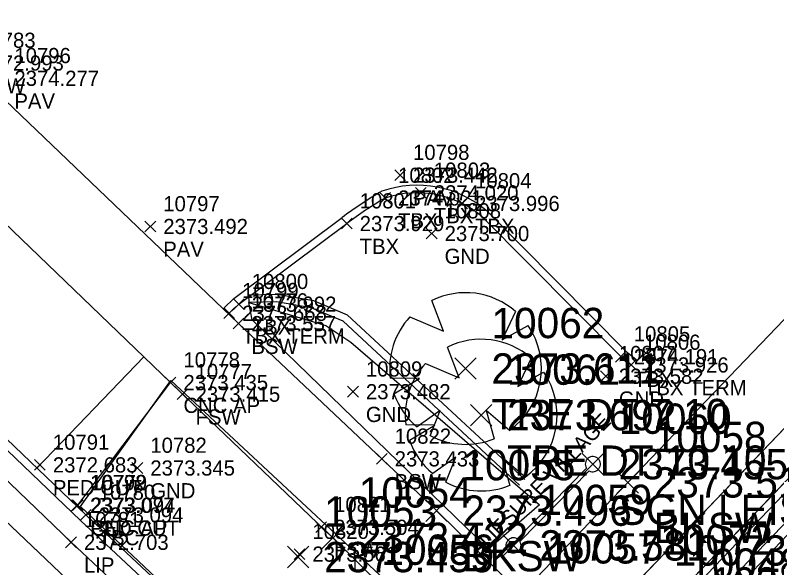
# Model space of a CAD drawing. Extents: x 2377639 to 2379738, y 729875 to 732734.
# Drawn here: x 2378105.9 to 2378156.1, y 730392.7 to 730429.2 of the extents above; entities that cross this region are included whole.
import ezdxf

# ---------------------------------------------------------------- set-up
doc = ezdxf.new("R2010")
doc.units = 0
for name, color, linetype in [('Default', 7, 'Continuous'), ('TOPO_CURBGTR_Back-of-Curb', 7, 'Continuous'), ('TOPO_CURBGTR_Face-of-Curb', 7, 'Continuous'), ('TOPO_CURBGTR_Lip-of-Gutter', 7, 'Continuous'), ('TOPO_DATA_Elevations', 7, 'Continuous'), ('TOPO_DATA_Notes', 7, 'Continuous'), ('TOPO_LNDSCP_Bush-Boundary', 7, 'Continuous'), ('TOPO_LNDSCP_Misc', 7, 'Continuous'), ('TOPO_LNDSCP_Tree', 7, 'Continuous'), ('TOPO_MISC_Flat-Asphalt', 7, 'Continuous'), ('TOPO_SIGNS_Post-Single', 7, 'Continuous'), ('TOPO_SW_Back', 7, 'Continuous'), ('TOPO_WTRUTIL_Fire-Hydrant', 7, 'Continuous'), ('TOPO_WTRUTIL_Line', 7, 'Continuous')]:
    doc.layers.add(name, color=color, linetype=linetype)

# ---------------------------------------------------------------- blocks, each defined once
blk = doc.blocks.new('DT_1')
at = {"layer": 'Default'}
for p, q in [((-0.037, 0.0625), (-0.0565, 0.1137)), ((0.0838, 0.0954), (0.0615, 0.0479)), ((-0.093, 0.0865), (-0.037, 0.0625)), ((0.0615, 0.0479), (0.1046, 0.072)), ((-0.0773, -0.017), (-0.1259, -0.0164)), ((-0.1198, -0.0422), (-0.0773, -0.017)), ((-0.0426, -0.0702), (-0.0811, -0.0977)), ((-0.059, -0.1125), (-0.0426, -0.0702)), ((0.0734, -0.1037), (0.0346, -0.0702)), ((0.0346, -0.0702), (0.048, -0.1176))]:
    blk.add_line(p, q, dxfattribs=at)
for start, end in [(48.7013, 116.3979), (137.0682, 187.4038), (305.2865, 34.5379), (199.3985, 230.3084), (242.3287, 292.2114)]:
    blk.add_arc((0, 0), 0.127, start, end, dxfattribs=at)

msp = doc.modelspace()

# ---------------------------------------------------------------- linework, layer by layer
at = {"layer": 'TOPO_CURBGTR_Back-of-Curb'}
for points in [[(2378139.753, 730380.865), (2378148.64, 730389.997), (2378225.837, 730470.65), (2378251.518, 730497.426), (2378309.295, 730557.655), (2378317.456, 730566.28)], [(2378136.696, 730415.869), (2378145.842, 730406.642), (2378146.514, 730406.094)], [(2378119.279, 730388.079), (2378110.587, 730396.202), (2378090.198, 730415.739)], [(2378120.038, 730409.502), (2378120.67, 730410.101), (2378127.78, 730415.416)], [(2378121.318, 730410.715), (2378123.198, 730410.754), (2378125.58, 730410.338), (2378127.817, 730409.406), (2378139.51, 730398.53)]]:
    msp.add_lwpolyline(points, dxfattribs=at)
for centre, radius, start, end in [((2378132.413, 730410.83), 6.613, 49.635, 108.5304), ((2378144.472, 730393.087), 27.879, 120.5274, 126.7795)]:
    msp.add_arc(centre, radius, start, end, dxfattribs=at)
at = {"layer": 'TOPO_CURBGTR_Face-of-Curb'}
msp.add_line((2378121.318, 730410.715), (2378121.328, 730410.215), dxfattribs=at)
for points in [[(2378140.262, 730380.667), (2378149, 730389.65), (2378226.198, 730470.304), (2378251.879, 730497.08), (2378309.657, 730557.31), (2378317.819, 730565.936)], [(2378119.694, 730409.865), (2378120.347, 730410.484), (2378127.481, 730415.816)], [(2378137.036, 730416.236), (2378146.178, 730407.013), (2378146.83, 730406.481)], [(2378118.938, 730387.713), (2378110.243, 730395.839), (2378089.852, 730415.378)], [(2378139.169, 730398.164), (2378127.542, 730408.979), (2378125.439, 730409.855), (2378123.16, 730410.254), (2378121.328, 730410.215)]]:
    msp.add_lwpolyline(points, dxfattribs=at)
for centre, radius, start, end in [((2378132.413, 730410.83), 7.113, 49.4599, 108.9593), ((2378144.472, 730393.087), 28.379, 120.4228, 126.7795)]:
    msp.add_arc(centre, radius, start, end, dxfattribs=at)
at = {"layer": 'TOPO_CURBGTR_Lip-of-Gutter'}
for points in [[(2378319.904, 730566.205), (2378310.745, 730556.446), (2378281.259, 730525.513), (2378150.03, 730388.754), (2378141.734, 730380.114)], [(2378088.895, 730414.34), (2378109.615, 730394.398), (2378117.945, 730386.574)]]:
    msp.add_lwpolyline(points, dxfattribs=at)
at = {"layer": 'TOPO_DATA_Elevations'}
for p, q in [((2378130.941, 730418.258), (2378131.649, 730418.966)), ((2378130.941, 730418.966), (2378131.649, 730418.258)), ((2378130.941, 730418.258), (2378131.649, 730418.966)), ((2378130.941, 730418.966), (2378131.649, 730418.258)), ((2378129.957, 730416.747), (2378130.665, 730417.455)), ((2378129.957, 730417.455), (2378130.665, 730416.747)), ((2378129.957, 730416.747), (2378130.665, 730417.455)), ((2378129.957, 730417.455), (2378130.665, 730416.747)), ((2378132.311, 730417.085), (2378133.019, 730417.793)), ((2378132.311, 730417.793), (2378133.019, 730417.085)), ((2378132.311, 730417.085), (2378133.019, 730417.793)), ((2378132.311, 730417.793), (2378133.019, 730417.085)), ((2378135.029, 730416.387), (2378135.737, 730417.095)), ((2378135.029, 730417.095), (2378135.737, 730416.387)), ((2378135.029, 730416.387), (2378135.737, 730417.095)), ((2378135.029, 730417.095), (2378135.737, 730416.387)), ((2378114.484, 730414.872), (2378115.192, 730415.58)), ((2378114.484, 730415.58), (2378115.192, 730414.872)), ((2378114.484, 730414.872), (2378115.192, 730415.58)), ((2378114.484, 730415.58), (2378115.192, 730414.872)), ((2378127.426, 730415.062), (2378128.134, 730415.77)), ((2378127.426, 730415.77), (2378128.134, 730415.062)), ((2378127.426, 730415.062), (2378128.134, 730415.77)), ((2378127.426, 730415.77), (2378128.134, 730415.062)), ((2378133.022, 730414.404), (2378133.73, 730415.112)), ((2378133.022, 730415.112), (2378133.73, 730414.404)), ((2378133.022, 730414.404), (2378133.73, 730415.112)), ((2378133.022, 730415.112), (2378133.73, 730414.404)), ((2378120.316, 730409.747), (2378121.024, 730410.455)), ((2378120.316, 730410.455), (2378121.024, 730409.747)), ((2378120.316, 730409.747), (2378121.024, 730410.455)), ((2378120.316, 730410.455), (2378121.024, 730409.747)), ((2378119.684, 730409.148), (2378120.392, 730409.856)), ((2378119.684, 730409.856), (2378120.392, 730409.148)), ((2378119.684, 730409.148), (2378120.392, 730409.856)), ((2378119.684, 730409.856), (2378120.392, 730409.148)), ((2378120.293, 730408.465), (2378121.001, 730409.173)), ((2378120.293, 730409.173), (2378121.001, 730408.465)), ((2378120.293, 730408.465), (2378121.001, 730409.173)), ((2378120.293, 730409.173), (2378121.001, 730408.465)), ((2378145.488, 730406.288), (2378146.196, 730406.996)), ((2378145.488, 730406.996), (2378146.196, 730406.288)), ((2378145.488, 730406.288), (2378146.196, 730406.996)), ((2378145.488, 730406.996), (2378146.196, 730406.288)), ((2378134.902, 730405.152), (2378136.316, 730406.566)), ((2378134.902, 730406.566), (2378136.316, 730405.152)), ((2378146.16, 730405.74), (2378146.868, 730406.448)), ((2378146.16, 730406.448), (2378146.868, 730405.74)), ((2378146.16, 730405.74), (2378146.868, 730406.448)), ((2378146.16, 730406.448), (2378146.868, 730405.74)), ((2378115.814, 730404.577), (2378116.522, 730405.285)), ((2378115.814, 730405.285), (2378116.522, 730404.577)), ((2378115.814, 730404.577), (2378116.522, 730405.285)), ((2378115.814, 730405.285), (2378116.522, 730404.577)), ((2378144.504, 730404.995), (2378145.212, 730405.703)), ((2378144.504, 730405.703), (2378145.212, 730404.995)), ((2378144.504, 730404.995), (2378145.212, 730405.703)), ((2378144.504, 730405.703), (2378145.212, 730404.995)), ((2378116.612, 730403.812), (2378117.32, 730404.52)), ((2378116.612, 730404.52), (2378117.32, 730403.812)), ((2378116.612, 730403.812), (2378117.32, 730404.52)), ((2378116.612, 730404.52), (2378117.32, 730403.812)), ((2378127.837, 730403.976), (2378128.545, 730404.684)), ((2378127.837, 730404.684), (2378128.545, 730403.976)), ((2378127.837, 730403.976), (2378128.545, 730404.684)), ((2378127.837, 730404.684), (2378128.545, 730403.976)), ((2378135.931, 730402.078), (2378137.345, 730403.492)), ((2378135.931, 730403.492), (2378137.345, 730402.078)), ((2378143.289, 730398.844), (2378144.703, 730400.258)), ((2378143.289, 730400.258), (2378144.703, 730398.844)), ((2378107.209, 730399.149), (2378107.917, 730399.857)), ((2378107.209, 730399.857), (2378107.917, 730399.149)), ((2378107.209, 730399.149), (2378107.917, 730399.857)), ((2378107.209, 730399.857), (2378107.917, 730399.149)), ((2378129.732, 730399.546), (2378130.439, 730400.254)), ((2378129.732, 730400.254), (2378130.439, 730399.546)), ((2378129.732, 730399.546), (2378130.439, 730400.254)), ((2378129.732, 730400.254), (2378130.439, 730399.546)), ((2378113.631, 730398.945), (2378114.339, 730399.653)), ((2378113.631, 730399.653), (2378114.339, 730398.945)), ((2378113.631, 730398.945), (2378114.339, 730399.653)), ((2378113.631, 730399.653), (2378114.339, 730398.945)), ((2378145.593, 730397.642), (2378147.007, 730399.056)), ((2378145.593, 730399.056), (2378147.007, 730397.642)), ((2378109.655, 730396.482), (2378110.363, 730397.19)), ((2378109.655, 730397.19), (2378110.363, 730396.482)), ((2378109.655, 730396.482), (2378110.363, 730397.19)), ((2378109.655, 730397.19), (2378110.363, 730396.482)), ((2378109.703, 730396.492), (2378110.411, 730397.2)), ((2378109.703, 730397.2), (2378110.411, 730396.492)), ((2378109.703, 730396.492), (2378110.411, 730397.2)), ((2378109.703, 730397.2), (2378110.411, 730396.492)), ((2378132.991, 730395.779), (2378134.405, 730397.193)), ((2378132.991, 730397.193), (2378134.405, 730395.779)), ((2378110.233, 730395.848), (2378110.941, 730396.556)), ((2378110.233, 730396.556), (2378110.941, 730395.848)), ((2378110.233, 730395.848), (2378110.941, 730396.556)), ((2378110.233, 730396.556), (2378110.941, 730395.848)), ((2378125.739, 730395.035), (2378126.447, 730395.743)), ((2378125.739, 730395.743), (2378126.447, 730395.035)), ((2378125.739, 730395.035), (2378126.447, 730395.743)), ((2378125.739, 730395.743), (2378126.447, 730395.035)), ((2378126.165, 730393.982), (2378127.579, 730395.396)), ((2378126.165, 730395.396), (2378127.579, 730393.982)), ((2378109.261, 730394.044), (2378109.969, 730394.752)), ((2378109.261, 730394.752), (2378109.969, 730394.044)), ((2378109.261, 730394.044), (2378109.969, 730394.752)), ((2378109.261, 730394.752), (2378109.969, 730394.044)), ((2378138.061, 730393.488), (2378139.475, 730394.902)), ((2378138.061, 730394.902), (2378139.475, 730393.488)), ((2378123.878, 730392.72), (2378125.292, 730394.134)), ((2378123.878, 730394.134), (2378125.292, 730392.72)), ((2378124.31, 730393.268), (2378125.018, 730393.976)), ((2378124.31, 730393.976), (2378125.018, 730393.268)), ((2378124.31, 730393.268), (2378125.018, 730393.976)), ((2378124.31, 730393.976), (2378125.018, 730393.268))]:
    msp.add_line(p, q, dxfattribs=at)
at = {"layer": 'TOPO_LNDSCP_Bush-Boundary'}
msp.add_lwpolyline([(2378140.474, 730396.86), (2378137.112, 730393.94), (2378121.559, 730409.079), (2378121.328, 730410.215), (2378126.403, 730408.704), (2378128.056, 730407.592)], close=True, dxfattribs=at)
at = {"layer": 'TOPO_LNDSCP_Misc'}
for points in [[(2378110.246, 730396.771), (2378116.19, 730405.07), (2378135.663, 730386.918)], [(2378135.663, 730386.918), (2378128.606, 730379.436), (2378110.246, 730396.771)]]:
    msp.add_lwpolyline(points, dxfattribs=at)
at = {"layer": 'TOPO_MISC_Flat-Asphalt'}
msp.add_lwpolyline([(2378142.932, 730387.645), (2378190.637, 730437.477), (2378192.437, 730435.754), (2378144.732, 730385.922)], close=True, dxfattribs=at)
at = {"layer": 'TOPO_SIGNS_Post-Single'}
for p, q in [((2378143.568, 730399.292), (2378139.017, 730394.629)), ((2378139.196, 730394.454), (2378143.747, 730399.117))]:
    msp.add_line(p, q, dxfattribs=at)
for centre, start, end in [((2378143.996, 730399.551), 240.1704, 211.2154), ((2378138.768, 730394.195), 60.1704, 31.2154)]:
    msp.add_arc(centre, 0.5, start, end, dxfattribs=at)
at = {"layer": 'TOPO_SW_Back'}
for p, q in [((2378107.361, 730399.293), (2378114.412, 730406.621)), ((2378109.997, 730396.767), (2378116.168, 730404.931))]:
    msp.add_line(p, q, dxfattribs=at)
for points in [[(2378133.698, 730396.486), (2378139.263, 730391), (2378146.3, 730398.349), (2378224.625, 730480.085)], [(2378224.032, 730472.38), (2378146.723, 730391.578), (2378142.932, 730387.645), (2378144.689, 730385.936)], [(2378102.707, 730426.003), (2378120.647, 730408.819), (2378133.698, 730396.486)], [(2378126.872, 730394.689), (2378116.168, 730404.931), (2378097.08, 730423.299)], [(2378126.872, 730394.689), (2378135.063, 730386.614), (2378128.358, 730379.611)]]:
    msp.add_lwpolyline(points, dxfattribs=at)
at = {"layer": 'TOPO_WTRUTIL_Fire-Hydrant'}
msp.add_line((2378128.332, 730392.495), (2378128.309, 730394.078), dxfattribs=at)
at = {"layer": 'TOPO_WTRUTIL_Line'}
for p, q in [((2378133.356, 730370.41), (2378391.806, 730640.09)), ((2377982.698, 730512.231), (2378121.502, 730380.425))]:
    msp.add_line(p, q, dxfattribs=at)

# ---------------------------------------------------------------- block references
at = {"layer": 'TOPO_LNDSCP_Tree', "xscale": 39.370000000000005, "yscale": 39.370000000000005}
for p in [(2378135.609, 730405.859), (2378136.638, 730402.785)]:
    msp.add_blockref('DT_1', p, dxfattribs=at)

# ---------------------------------------------------------------- texts
at = {"layer": 'TOPO_DATA_Elevations'}
for s, height, p in [('10783', 1, (2378103.561, 730427.003)), ('10783', 1, (2378103.561, 730427.003)), ('10796', 1, (2378105.884, 730425.996)), ('10796', 1, (2378105.884, 730425.996)), ('2372.993', 1, (2378103.561, 730425.503)), ('2372.993', 1, (2378103.561, 730425.503)), ('2374.277', 1, (2378105.884, 730424.496)), ('2374.277', 1, (2378105.884, 730424.496)), ('BSW', 1, (2378103.561, 730424.003)), ('BSW', 1, (2378103.561, 730424.003)), ('PAV', 1, (2378105.884, 730422.996)), ('PAV', 1, (2378105.884, 730422.996)), ('10798', 1, (2378132.149, 730419.612)), ('10798', 1, (2378132.149, 730419.612)), ('10803', 1, (2378133.519, 730418.439)), ('10803', 1, (2378133.519, 730418.439)), ('10802', 1, (2378131.165, 730418.101)), ('10802', 1, (2378131.165, 730418.101)), ('2373.442', 1, (2378132.149, 730418.112)), ('2373.442', 1, (2378132.149, 730418.112)), ('10804', 1, (2378136.237, 730417.741)), ('10804', 1, (2378136.237, 730417.741)), ('2374.020', 1, (2378133.519, 730416.939)), ('2374.020', 1, (2378133.519, 730416.939)), ('10801', 1, (2378128.634, 730416.416)), ('10801', 1, (2378128.634, 730416.416)), ('2374.021', 1, (2378131.165, 730416.601)), ('2374.021', 1, (2378131.165, 730416.601)), ('PAV', 1, (2378132.149, 730416.612)), ('PAV', 1, (2378132.149, 730416.612)), ('10797', 1, (2378115.692, 730416.226)), ('10797', 1, (2378115.692, 730416.226)), ('2373.996', 1, (2378136.237, 730416.241)), ('2373.996', 1, (2378136.237, 730416.241)), ('TBX', 1, (2378133.519, 730415.439)), ('TBX', 1, (2378133.519, 730415.439)), ('10808', 1, (2378134.23, 730415.758)), ('10808', 1, (2378134.23, 730415.758)), ('2373.929', 1, (2378128.634, 730414.916)), ('2373.929', 1, (2378128.634, 730414.916)), ('TBX', 1, (2378131.165, 730415.101)), ('TBX', 1, (2378131.165, 730415.101)), ('2373.492', 1, (2378115.692, 730414.726)), ('2373.492', 1, (2378115.692, 730414.726)), ('TBX', 1, (2378136.237, 730414.741)), ('TBX', 1, (2378136.237, 730414.741)), ('2373.700', 1, (2378134.23, 730414.258)), ('2373.700', 1, (2378134.23, 730414.258)), ('TBX', 1, (2378128.634, 730413.416)), ('TBX', 1, (2378128.634, 730413.416)), ('PAV', 1, (2378115.692, 730413.226)), ('PAV', 1, (2378115.692, 730413.226)), ('GND', 1, (2378134.23, 730412.758)), ('GND', 1, (2378134.23, 730412.758)), ('10800', 1, (2378121.524, 730411.101)), ('10800', 1, (2378121.524, 730411.101)), ('10799', 1, (2378120.892, 730410.502)), ('10799', 1, (2378120.892, 730410.502)), ('10776', 1, (2378121.501, 730409.819)), ('10776', 1, (2378121.501, 730409.819)), ('2373.992', 1, (2378121.524, 730409.601)), ('2373.992', 1, (2378121.524, 730409.601)), ('2373.668', 1, (2378120.892, 730409.002)), ('2373.668', 1, (2378120.892, 730409.002)), ('10062', 2, (2378137.316, 730407.859)), ('2373.557', 1, (2378121.501, 730408.319)), ('2373.557', 1, (2378121.501, 730408.319)), ('TBX', 1, (2378121.524, 730408.101)), ('TBX', 1, (2378121.524, 730408.101)), ('TBX TERM', 1, (2378120.892, 730407.502)), ('TBX TERM', 1, (2378120.892, 730407.502)), ('10805', 1, (2378146.696, 730407.642)), ('10805', 1, (2378146.696, 730407.642)), ('BSW', 1, (2378121.501, 730406.819)), ('BSW', 1, (2378121.501, 730406.819)), ('10806', 1, (2378147.368, 730407.094)), ('10806', 1, (2378147.368, 730407.094)), ('10807', 1, (2378145.712, 730406.349)), ('10807', 1, (2378145.712, 730406.349)), ('10778', 1, (2378117.022, 730405.931)), ('10778', 1, (2378117.022, 730405.931)), ('2373.611', 2, (2378137.316, 730404.859)), ('10061', 2, (2378138.345, 730404.785)), ('2374.191', 1, (2378146.696, 730406.142)), ('2374.191', 1, (2378146.696, 730406.142)), ('10809', 1, (2378129.045, 730405.33)), ('10809', 1, (2378129.045, 730405.33)), ('2373.926', 1, (2378147.368, 730405.594)), ('2373.926', 1, (2378147.368, 730405.594)), ('10777', 1, (2378117.82, 730405.166)), ('10777', 1, (2378117.82, 730405.166)), ('2373.582', 1, (2378145.712, 730404.849)), ('2373.582', 1, (2378145.712, 730404.849)), ('2373.435', 1, (2378117.022, 730404.431)), ('2373.435', 1, (2378117.022, 730404.431)), ('TBX', 1, (2378146.696, 730404.642)), ('TBX', 1, (2378146.696, 730404.642)), ('2373.482', 1, (2378129.045, 730403.83)), ('2373.482', 1, (2378129.045, 730403.83)), ('TBX TERM', 1, (2378147.368, 730404.094)), ('TBX TERM', 1, (2378147.368, 730404.094)), ('2373.415', 1, (2378117.82, 730403.666)), ('2373.415', 1, (2378117.82, 730403.666)), ('GND', 1, (2378145.712, 730403.349)), ('GND', 1, (2378145.712, 730403.349)), ('CNC AP', 1, (2378117.022, 730402.931)), ('CNC AP', 1, (2378117.022, 730402.931)), ('TRE DT 7 10', 2, (2378137.316, 730401.859)), ('2373.692', 2, (2378138.345, 730401.785)), ('GND', 1, (2378129.045, 730402.33)), ('GND', 1, (2378129.045, 730402.33)), ('10060', 2, (2378145.703, 730401.551)), ('FSW', 1, (2378117.82, 730402.166)), ('FSW', 1, (2378117.82, 730402.166)), ('10058', 2, (2378148.007, 730400.349)), ('10822', 1, (2378130.939, 730400.9)), ('10822', 1, (2378130.939, 730400.9)), ('10791', 1, (2378108.417, 730400.503)), ('10791', 1, (2378108.417, 730400.503)), ('10782', 1, (2378114.839, 730400.299)), ('10782', 1, (2378114.839, 730400.299)), ('TRE DT 10 10', 2, (2378138.345, 730398.785)), ('2373.433', 1, (2378130.939, 730399.4)), ('2373.433', 1, (2378130.939, 730399.4)), ('10055', 2, (2378135.405, 730398.486)), ('2373.455', 2, (2378145.703, 730398.551)), ('2372.683', 1, (2378108.417, 730399.003)), ('2372.683', 1, (2378108.417, 730399.003)), ('2373.345', 1, (2378114.839, 730398.799)), ('2373.345', 1, (2378114.839, 730398.799)), ('2373.512', 2, (2378148.007, 730397.349)), ('10792', 1, (2378110.863, 730397.836)), ('10792', 1, (2378110.863, 730397.836)), ('10779', 1, (2378110.911, 730397.846)), ('10779', 1, (2378110.911, 730397.846)), ('BSW', 1, (2378130.939, 730397.9)), ('BSW', 1, (2378130.939, 730397.9)), ('PED CUT', 1, (2378108.417, 730397.503)), ('PED CUT', 1, (2378108.417, 730397.503)), ('GND', 1, (2378114.839, 730397.299)), ('GND', 1, (2378114.839, 730397.299)), ('10054', 2, (2378128.579, 730396.689)), ('10780', 1, (2378111.441, 730397.202)), ('10780', 1, (2378111.441, 730397.202)), ('10059', 2, (2378140.475, 730396.195)), ('2373.077', 1, (2378110.863, 730396.336)), ('2373.077', 1, (2378110.863, 730396.336)), ('2373.094', 1, (2378110.911, 730396.346)), ('2373.094', 1, (2378110.911, 730396.346)), ('10053', 2, (2378126.292, 730395.427)), ('10821', 1, (2378126.947, 730396.389)), ('10821', 1, (2378126.947, 730396.389)), ('2373.496', 2, (2378135.405, 730395.486)), ('SGN LEISURE VILLAGE', 2, (2378145.703, 730395.551)), ('10781', 1, (2378110.469, 730395.398)), ('10781', 1, (2378110.469, 730395.398)), ('2373.094', 1, (2378111.441, 730395.702)), ('2373.094', 1, (2378111.441, 730395.702)), ('BKSW', 2, (2378148.007, 730394.349)), ('PED CUT', 1, (2378110.863, 730394.836)), ('PED CUT', 1, (2378110.863, 730394.836)), ('CNC AP', 1, (2378110.911, 730394.846)), ('CNC AP', 1, (2378110.911, 730394.846)), ('2373.504', 1, (2378126.947, 730394.889)), ('2373.504', 1, (2378126.947, 730394.889)), ('10820', 1, (2378125.518, 730394.622)), ('10820', 1, (2378125.518, 730394.622)), ('2373.422', 2, (2378128.579, 730393.689)), ('10072', 2, (2378148.43, 730393.578)), ('2372.703', 1, (2378110.469, 730393.898)), ('2372.703', 1, (2378110.469, 730393.898)), ('TBC', 1, (2378111.441, 730394.202)), ('TBC', 1, (2378111.441, 730394.202)), ('10056', 2, (2378130.063, 730392.911)), ('2373.581', 2, (2378140.475, 730393.195)), ('10057', 2, (2378140.97, 730393)), ('10073', 2, (2378149.333, 730392.862)), ('2373.455', 2, (2378126.292, 730392.427)), ('FSW', 1, (2378126.947, 730393.389)), ('FSW', 1, (2378126.947, 730393.389)), ('BKSW', 2, (2378135.405, 730392.486)), ('2373.561', 1, (2378125.518, 730393.122)), ('2373.561', 1, (2378125.518, 730393.122)), ('10048', 2, (2378150.347, 730391.997)), ('LIP', 1, (2378110.469, 730392.398)), ('LIP', 1, (2378110.469, 730392.398)), ('10049', 2, (2378151.737, 730390.754))]:
    msp.add_text(s, height=height, dxfattribs=at).set_placement(p)
at = {"layer": 'TOPO_DATA_Notes'}
msp.add_text('LIESURE VILLAGE', height=1, rotation=45.6929, dxfattribs=at).set_placement((2378137.112, 730393.94))

doc.saveas('drawing.dxf')
